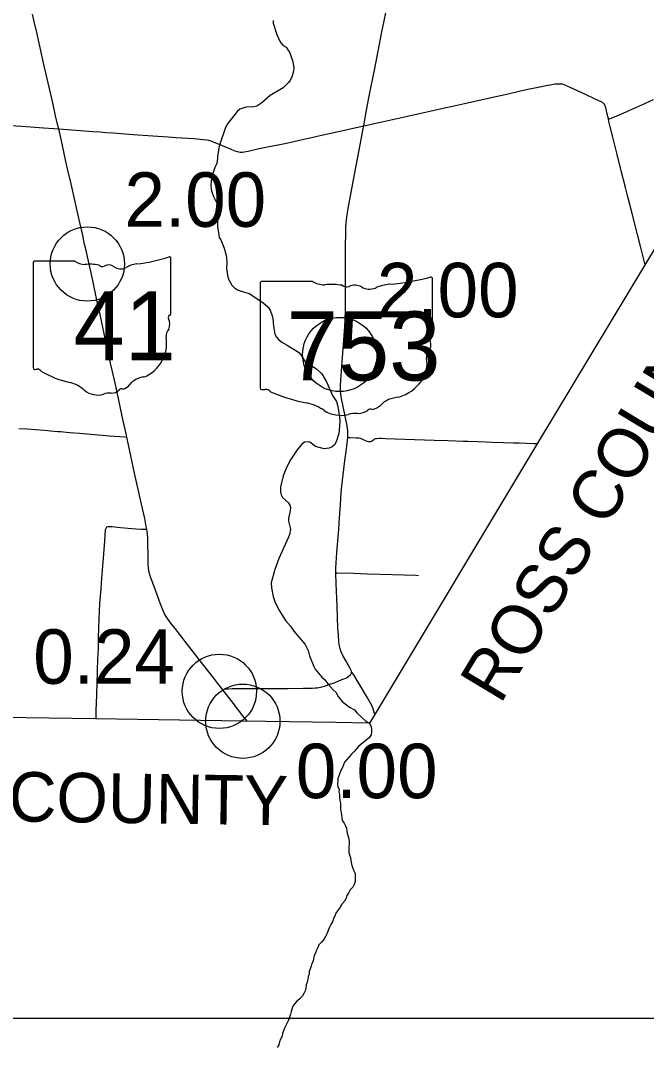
# Model space of a CAD drawing. Extents: x 1597222 to 1925846, y 496284 to 911751.
# Drawn here: x 1714792 to 1727439, y 496284 to 517019 of the extents above; entities that cross this region are included whole.
import ezdxf

# ---------------------------------------------------------------- set-up
doc = ezdxf.new("R2010")
doc.units = 0
for name, color, linetype in [('Default', 7, 'Continuous'), ('GM_X_Adjacent_County', 7, 'Continuous'), ('GM_X_Adjacent_County_Text', 7, 'Continuous'), ('GM_X_County', 7, 'Continuous'), ('GM_X_State_Route', 7, 'Continuous'), ('GM_X_State_Shield', 7, 'Continuous'), ('GM_X_Township', 7, 'Continuous'), ('GM_X_Township_Road', 7, 'Continuous'), ('SC_Scratch1', 7, 'Continuous')]:
    doc.layers.add(name, color=color, linetype=linetype)

msp = doc.modelspace()

# ---------------------------------------------------------------- linework, layer by layer
at = {"layer": 'Default'}
for centre in [(1716142, 512104), (1716142, 512104), (1721242, 510276), (1721242, 510276), (1718810, 503475), (1718810, 503475), (1719283, 502871), (1719283, 502871)]:
    msp.add_circle(centre, 750, dxfattribs=at)
at = {"layer": 'GM_X_Adjacent_County'}
msp.add_lwpolyline([(1721844, 502834), (1721877, 502756), (1721884, 502706), (1721883, 502652), (1721875, 502598), (1721834, 502539), (1721783, 502498), (1721726, 502449), (1721675, 502411), (1721622, 502364), (1721574, 502307), (1721527, 502254), (1721482, 502203), (1721434, 502152), (1721385, 502098), (1721340, 502043), (1721320, 501992), (1721300, 501939), (1721265, 501875), (1721245, 501822), (1721220, 501768), (1721206, 501715), (1721203, 501665), (1721197, 501601), (1721204, 501550), (1721227, 501500), (1721225, 501443), (1721236, 501389), (1721238, 501335), (1721244, 501270), (1721257, 501216), (1721255, 501158), (1721255, 501084), (1721270, 501031), (1721274, 500975), (1721281, 500921), (1721293, 500868), (1721334, 500813), (1721356, 500762), (1721375, 500710), (1721383, 500647), (1721398, 500585), (1721420, 500522), (1721432, 500449), (1721430, 500391), (1721427, 500337), (1721425, 500279), (1721428, 500223), (1721442, 500172), (1721461, 500118), (1721463, 500067), (1721470, 500017), (1721484, 499959), (1721503, 499904), (1721524, 499851), (1721550, 499796), (1721555, 499744), (1721555, 499690), (1721550, 499634), (1721530, 499576), (1721505, 499521), (1721455, 499464), (1721426, 499413), (1721386, 499352), (1721371, 499300), (1721335, 499237), (1721283, 499178), (1721250, 499117), (1721166, 498995), (1721140, 498940), (1721113, 498880), (1721094, 498822), (1721063, 498767), (1721034, 498713), (1721007, 498646), (1720980, 498580), (1720955, 498528), (1720919, 498463), (1720871, 498412), (1720819, 498355), (1720799, 498303), (1720774, 498249), (1720750, 498194), (1720727, 498136), (1720714, 498082), (1720703, 498030), (1720678, 497977), (1720663, 497925), (1720646, 497871), (1720625, 497817), (1720621, 497767), (1720605, 497711), (1720594, 497658), (1720583, 497606), (1720566, 497546), (1720557, 497484), (1720544, 497430), (1720517, 497376), (1720486, 497325), (1720437, 497268), (1720380, 497223), (1720335, 497169), (1720294, 497116), (1720273, 497060), (1720262, 497008), (1720249, 496955), (1720224, 496897), (1720207, 496835), (1720182, 496781), (1720155, 496726), (1720126, 496672), (1720103, 496619), (1720088, 496563), (1720075, 496511), (1720042, 496453), (1720023, 496398), (1720010, 496338), (1719979, 496284)], dxfattribs=at)
at = {"layer": 'GM_X_County'}
msp.add_lwpolyline([(1729526, 515601), (1727396, 512075), (1725220, 508449), (1721935, 502985), (1721844, 502834), (1721165, 502848), (1719280, 502875), (1716307, 502917), (1714432, 502944), (1711386, 502989), (1707043, 503052), (1704566, 503090), (1704437, 503092), (1698641, 503176), (1693676, 503248), (1687539, 503338), (1685835, 503363), (1685430, 503373), (1682405, 503448), (1678903, 503534), (1673166, 503675)], dxfattribs=at)
at = {"layer": 'GM_X_State_Route'}
for points in [[(1718881, 503506), (1718778, 503635), (1718699, 503739), (1718396, 504127), (1718216, 504361), (1718004, 504632), (1717923, 504736), (1717851, 504825), (1717762, 504943), (1717735, 504984), (1717710, 505027), (1717687, 505071), (1717661, 505132), (1717614, 505254), (1717489, 505593), (1717432, 505747), (1717412, 505809), (1717394, 505873), (1717384, 505921), (1717378, 505970), (1717374, 506036), (1717370, 506184), (1717366, 506495), (1717362, 506577), (1717357, 506642), (1717349, 506707), (1717343, 506748), (1717333, 506804), (1717301, 506965), (1717237, 507253), (1717098, 507877), (1717022, 508230), (1716974, 508455), (1716940, 508608), (1716931, 508647), (1716868, 508935), (1716811, 509191), (1716777, 509351), (1716751, 509480), (1716709, 509672), (1716644, 509960), (1716613, 510104), (1716537, 510457), (1716490, 510665), (1716398, 511081), (1716336, 511370), (1716250, 511770), (1716198, 512011), (1716173, 512128), (1716124, 512347), (1716087, 512507), (1716042, 512715), (1715992, 512939), (1715938, 513179), (1715815, 513723), (1715744, 514027), (1715710, 514170), (1715676, 514331), (1715618, 514587), (1715563, 514831), (1715560, 514843), (1715501, 515098), (1715443, 515354), (1715371, 515674), (1715272, 516106), (1715218, 516346), (1715118, 516777), (1715068, 517001), (1715035, 517145)], [(1721222, 506739), (1721233, 506881), (1721256, 507241), (1721270, 507487), (1721281, 507617), (1721308, 507845), (1721323, 507959), (1721346, 508138), (1721369, 508316), (1721396, 508544), (1721403, 508598), (1721404, 508633), (1721404, 508664), (1721402, 508726), (1721396, 508791), (1721377, 508905), (1721283, 509354), (1721265, 509467), (1721258, 509549), (1721257, 509647), (1721263, 509761), (1721285, 510039), (1721304, 510301), (1721333, 510660), (1721347, 510840), (1721354, 510971), (1721360, 511201), (1721361, 511414), (1721360, 511693), (1721358, 511840), (1721358, 512004), (1721360, 512201), (1721361, 512480), (1721363, 512709), (1721366, 512857), (1721375, 512987), (1721389, 513101), (1721418, 513262), (1721568, 514052), (1721607, 514261), (1721675, 514616), (1721717, 514841), (1721727, 514891), (1721770, 515132), (1721826, 515422), (1721879, 515695), (1721934, 515985), (1721977, 516194), (1722019, 516403), (1722095, 516789), (1722139, 517015), (1722172, 517175)], [(1721168, 506065), (1721183, 506276), (1721217, 506668), (1721222, 506739)], [(1718881, 503506), (1718910, 503519), (1718933, 503524), (1718957, 503526), (1718984, 503527), (1719066, 503529), (1719624, 503531), (1720197, 503535), (1720509, 503536), (1720655, 503539), (1720694, 503540), (1720747, 503544), (1720788, 503547), (1720821, 503551), (1720853, 503558), (1720888, 503566), (1720932, 503581), (1721020, 503611), (1721150, 503656), (1721286, 503711), (1721362, 503744), (1721388, 503757), (1721420, 503776), (1721442, 503793), (1721459, 503809), (1721468, 503822), (1721473, 503832), (1721476, 503841), (1721479, 503855), (1721478, 503871), (1721476, 503884), (1721473, 503895), (1721467, 503909), (1721452, 503939), (1721370, 504082), (1721305, 504196), (1721271, 504270), (1721249, 504331), (1721235, 504395), (1721223, 504475), (1721214, 504606), (1721206, 504753), (1721189, 505196), (1721167, 505655), (1721160, 505851), (1721161, 505870), (1721161, 505966), (1721168, 506065)], [(1719368, 502873), (1719285, 502981), (1719176, 503123), (1719046, 503291), (1718881, 503506)]]:
    msp.add_lwpolyline(points, dxfattribs=at)
at = {"layer": 'GM_X_State_Shield'}
for p, q in [((1715890, 512162), (1715074, 512162)), ((1717831, 511108), (1717831, 512214)), ((1715047, 512125), (1715047, 510012)), ((1720688, 511752), (1719669, 511752)), ((1723115, 510699), (1723115, 511805)), ((1719634, 511716), (1719634, 509603)), ((1717831, 511109), (1717831, 511108)), ((1723114, 510700), (1723115, 510699))]:
    msp.add_line(p, q, dxfattribs=at)
for centre, radius, start, end in [((1715079, 512130), 32.3, 98.1301, 188.1301), ((1716084, 512407), 313, 231.6195, 271.1119), ((1716839, 515043), 2953, 275.8445, 288.9065), ((1717800, 512219), 31, 351.8621, 97.738), ((1716187, 510975), 1123, 80.4867, 94.9883), ((1716442, 512141), 90.3, 219.7921, 297.1024), ((1716575, 511896), 188, 54.4667, 119.1411), ((1716817, 512231), 226, 233.8562, 294.8282), ((1717216, 511516), 594, 97.3462, 120.7689), ((1717824, 511027), 48, 107.944, 210.337), ((1717519, 510888), 288, 340.033, 23.6496), ((1717798, 511104), 33.2, 289.6038, 7.7341), ((1717942, 510646), 210, 136.8065, 186.9296), ((1717005, 510505), 739, 292.3089, 8.9858), ((1715079, 510007), 32.5, 171.9584, 258.3066), ((1715084, 510224), 248, 267.339, 280.6039), ((1715135, 509890), 89.5, 29.7484, 93.2717), ((1716265, 511789), 2132, 240.4129, 257.1985), ((1715629, 509063), 667, 47.1842, 75.836), ((1716804, 509807), 239, 282.8732, 323.2771), ((1717316, 509419), 404, 94.4031, 142.5768), ((1716351, 509880), 423, 230.7004, 286.2918), ((1716596, 509149), 348, 85.6951, 111.2099), ((1716627, 509721), 226, 268.777, 315.5493), ((1716831, 509517), 63.5, 65.7517, 132.6484)]:
    msp.add_arc(centre, radius, start, end, dxfattribs=at)
for centre, major_axis, start_param, end_param in [((1719674, 511720), (40.3, 0), 1.712693, 3.28349), ((1720931, 511998), (391, 0), 4.042523, 4.731795), ((1721875, 514633), (3691, 0), 4.814394, 5.042369), ((1723076, 511809), (38.7, 0), 6.141152, 7.989035), ((1721060, 510566), (1404, 0), 1.404758, 1.657858), ((1721379, 511731), (113, 0), 3.836095, 5.185415), ((1721545, 511487), (235, 0), 0.950623, 2.079405), ((1721847, 511822), (282, 0), 4.081561, 5.145723), ((1722346, 511107), (743, 0), 1.699011, 2.107814), ((1723073, 510695), (41.5, 0), 5.05454, 6.418171), ((1723106, 510618), (60, 0), 1.883978, 3.671073), ((1722724, 510478), (360, 0), 5.934695, 6.695948), ((1723254, 510237), (262, 0), 2.387724, 3.262537), ((1722082, 510096), (923, 0), 5.101752, 6.440018), ((1719675, 509598), (40.7, 0), 3.00124, 4.508301), ((1719681, 509814), (310, 0), 4.665946, 4.897461), ((1719744, 509481), (112, 0), 0.519207, 1.627899), ((1721157, 511379), (2665, 0), 4.195997, 4.488961), ((1720363, 508653), (834, 0), 0.823519, 1.323587), ((1721830, 509398), (298, 0), 4.937069, 5.64225), ((1722471, 509009), (506, 0), 1.647645, 2.488434), ((1721265, 509470), (529, 0), 4.026481, 4.996735), ((1721571, 508740), (435, 0), 1.495662, 1.94098), ((1721609, 509312), (282, 0), 4.691044, 5.507374), ((1721864, 509107), (79.4, 0), 1.147584, 2.315152)]:
    msp.add_ellipse(centre, major_axis=major_axis, ratio=0.8, start_param=start_param, end_param=end_param, dxfattribs=at)
at = {"layer": 'GM_X_Township'}
msp.add_lwpolyline([(1719897, 517022), (1719896, 516968), (1719969, 516737), (1720016, 516626), (1720049, 516567), (1720099, 516515), (1720157, 516480), (1720196, 516429), (1720229, 516379), (1720289, 516214), (1720308, 516111), (1720312, 516053), (1720305, 515995), (1720271, 515877), (1720240, 515818), (1720208, 515766), (1720098, 515659), (1719834, 515506), (1719670, 515358), (1719567, 515293), (1719504, 515276), (1719344, 515268), (1719223, 515227), (1719168, 515182), (1718973, 514934), (1718936, 514856), (1718811, 514505), (1718802, 514447), (1718772, 514269), (1718763, 514159), (1718748, 514105), (1718715, 514054), (1718682, 513948), (1718646, 513786), (1718635, 513680), (1718653, 513573), (1718696, 513453), (1718753, 513344), (1718762, 513292), (1718769, 512861), (1718797, 512694), (1718808, 512640), (1718837, 512589), (1718906, 512424), (1718942, 512299), (1718955, 512235), (1718962, 512127), (1718952, 512011), (1718980, 511834), (1719002, 511784), (1719059, 511677), (1719114, 511622), (1719178, 511581), (1719229, 511561), (1719409, 511508), (1719687, 511326), (1719796, 511231), (1719834, 511174), (1719878, 511055), (1719890, 511001), (1719902, 510845), (1719930, 510686), (1719961, 510628), (1720013, 510569), (1720070, 510524), (1720182, 510467), (1720406, 510324), (1720456, 510269), (1720558, 510105), (1720614, 510066), (1720717, 510021), (1720771, 509988), (1720878, 509885), (1720974, 509725), (1721095, 509445), (1721173, 509328), (1721202, 509224), (1721238, 509017), (1721242, 508914), (1721223, 508680), (1721171, 508513), (1721136, 508455), (1721086, 508410), (1721031, 508386), (1720977, 508375), (1720927, 508371), (1720755, 508420), (1720640, 508509), (1720586, 508514), (1720530, 508505), (1720479, 508467), (1720384, 508354), (1720231, 508128), (1720150, 507962), (1720101, 507827), (1720056, 507659), (1720046, 507603), (1720044, 507501), (1720060, 507443), (1720087, 507386), (1720198, 507289), (1720236, 507236), (1720247, 507184), (1720242, 507128), (1720206, 506964), (1720203, 506908), (1720245, 506749), (1720226, 506639), (1720205, 506585), (1720012, 506157), (1719929, 505938), (1719859, 505668), (1719860, 505562), (1719896, 505393), (1719931, 505290), (1720009, 505119), (1720146, 504903), (1720249, 504789), (1720312, 504688), (1720541, 504419), (1720572, 504367), (1720602, 504296), (1720628, 504190), (1720718, 503974), (1720747, 503922), (1720881, 503760), (1720935, 503711), (1721011, 503622), (1721111, 503504), (1721168, 503449), (1721206, 503377), (1721288, 503268), (1721436, 503152), (1721538, 503099), (1721590, 503041), (1721770, 502872), (1721844, 502834), (1721165, 502848), (1719280, 502875), (1716307, 502917), (1714432, 502944)], dxfattribs=at)
at = {"layer": 'GM_X_Township_Road'}
for points in [[(1721727, 514891), (1721731, 514892), (1722067, 514968), (1722307, 515020), (1722611, 515088), (1722883, 515149), (1723059, 515189), (1723235, 515229), (1723395, 515264), (1723523, 515292), (1723763, 515345), (1723971, 515393), (1724243, 515453), (1724643, 515542), (1724867, 515593), (1725043, 515630), (1725219, 515669), (1725444, 515714), (1725525, 515729), (1725590, 515739), (1725640, 515743), (1725673, 515744), (1725706, 515743), (1725722, 515741), (1725739, 515738), (1725771, 515729), (1725802, 515717), (1725891, 515675), (1726040, 515606), (1726189, 515537), (1726412, 515434), (1726516, 515385), (1726545, 515368), (1726559, 515358), (1726571, 515347), (1726582, 515335), (1726591, 515320), (1726599, 515305), (1726605, 515290), (1726613, 515255), (1726640, 515138), (1726658, 515066), (1726669, 515026)], [(1726669, 515026), (1726760, 515060), (1726908, 515125), (1727043, 515185), (1727223, 515264), (1727403, 515345), (1727582, 515425)], [(1714583, 514899), (1714812, 514884), (1714992, 514872), (1715254, 514854), (1715467, 514838), (1715563, 514831)], [(1719052, 514417), (1719123, 514390), (1719169, 514374), (1719200, 514366), (1719232, 514361), (1719248, 514360), (1719280, 514361), (1719312, 514365), (1719392, 514382), (1719616, 514434), (1719745, 514461), (1720067, 514524), (1720227, 514558), (1720402, 514599), (1720514, 514625), (1720642, 514653), (1720786, 514686), (1721026, 514739), (1721154, 514767), (1721426, 514827), (1721634, 514873), (1721727, 514891)], [(1727413, 512086), (1727377, 512221), (1727329, 512412), (1727256, 512697), (1727147, 513125), (1727064, 513459), (1727016, 513649), (1726931, 513982), (1726847, 514315), (1726759, 514664), (1726707, 514871), (1726680, 514983), (1726669, 515026)], [(1715563, 514831), (1715827, 514811), (1716007, 514799), (1716252, 514779), (1716399, 514769), (1716513, 514761), (1716661, 514750), (1717070, 514721), (1717462, 514694), (1717773, 514671), (1717936, 514660), (1718051, 514652), (1718296, 514634), (1718492, 514619), (1718558, 514612), (1718590, 514605), (1718608, 514599)], [(1718608, 514599), (1718638, 514590), (1718699, 514566), (1718819, 514515)], [(1718819, 514515), (1718865, 514496), (1719047, 514420), (1719052, 514417)], [(1714758, 508785), (1714922, 508773), (1715085, 508759), (1715281, 508745), (1715396, 508736), (1715543, 508724), (1715608, 508719), (1715658, 508715), (1715788, 508704), (1715985, 508688), (1716213, 508668), (1716361, 508655), (1716442, 508648), (1716589, 508637), (1716900, 508611), (1716940, 508608)], [(1721403, 508598), (1721445, 508598), (1721575, 508596), (1721625, 508591), (1721657, 508584), (1721703, 508567), (1721791, 508526), (1721823, 508517), (1721839, 508515), (1721855, 508517), (1721870, 508521), (1721886, 508529), (1721901, 508538), (1721924, 508555), (1721939, 508565), (1721954, 508572), (1721969, 508577), (1721986, 508581), (1722036, 508586), (1722094, 508585), (1722167, 508582), (1722559, 508567), (1723149, 508548), (1723428, 508538), (1723737, 508527), (1723839, 508524), (1724037, 508516), (1724330, 508509), (1724552, 508500), (1724751, 508492), (1724869, 508489), (1725164, 508482), (1725240, 508481)], [(1716317, 502919), (1716317, 502927), (1716321, 503074), (1716328, 503254), (1716334, 503385), (1716336, 503450), (1716340, 503614), (1716347, 503893), (1716355, 504122), (1716358, 504220), (1716364, 504351), (1716370, 504564), (1716381, 504941), (1716387, 505088), (1716397, 505251), (1716419, 505546), (1716436, 505758), (1716461, 506085), (1716493, 506509), (1716512, 506738), (1716514, 506754), (1716519, 506770), (1716527, 506784), (1716539, 506796), (1716553, 506802), (1716570, 506805), (1716586, 506804), (1716635, 506800), (1716814, 506783), (1717125, 506757), (1717239, 506749), (1717288, 506748), (1717343, 506748)], [(1721161, 505870), (1721196, 505869), (1721523, 505860), (1721801, 505850), (1722309, 505833), (1722538, 505824), (1722782, 505819), (1722831, 505815)], [(1721950, 503005), (1721927, 503095), (1721912, 503142), (1721884, 503201), (1721803, 503344), (1721597, 503696), (1721525, 503808), (1721513, 503824), (1721499, 503839), (1721479, 503855)]]:
    msp.add_lwpolyline(points, dxfattribs=at)
at = {"layer": 'SC_Scratch1'}
msp.add_lwpolyline([(1597222, 631367), (1793472, 631367), (1793472, 496867), (1597222, 496867)], close=True, dxfattribs=at)

# ---------------------------------------------------------------- texts
at = {"layer": 'Default'}
for s, p in [('2.00', (1716892, 512854)), ('2.00', (1716892, 512854)), ('2.00', (1721992, 511026)), ('2.00', (1721992, 511026)), ('0.24', (1715049, 503627)), ('0.24', (1715049, 503627)), ('0.00', (1720355, 501318)), ('0.00', (1720355, 501318))]:
    msp.add_text(s, height=1100, dxfattribs=at).set_placement(p)
at = {"layer": 'GM_X_Adjacent_County_Text'}
for s, rotation, p in [('ROSS COUNTY', 58.9647, (1724485, 503194)), ('HIGHLAND COUNTY', 359.149, (1707265, 500959))]:
    msp.add_text(s, height=1000, rotation=rotation, dxfattribs=at).set_placement(p)
at = {"layer": 'GM_X_State_Shield'}
for s, p in [('41', (1715861, 510161)), ('753', (1720170, 509752))]:
    msp.add_text(s, height=1392.2, dxfattribs=at).set_placement(p)

doc.saveas('drawing.dxf')
